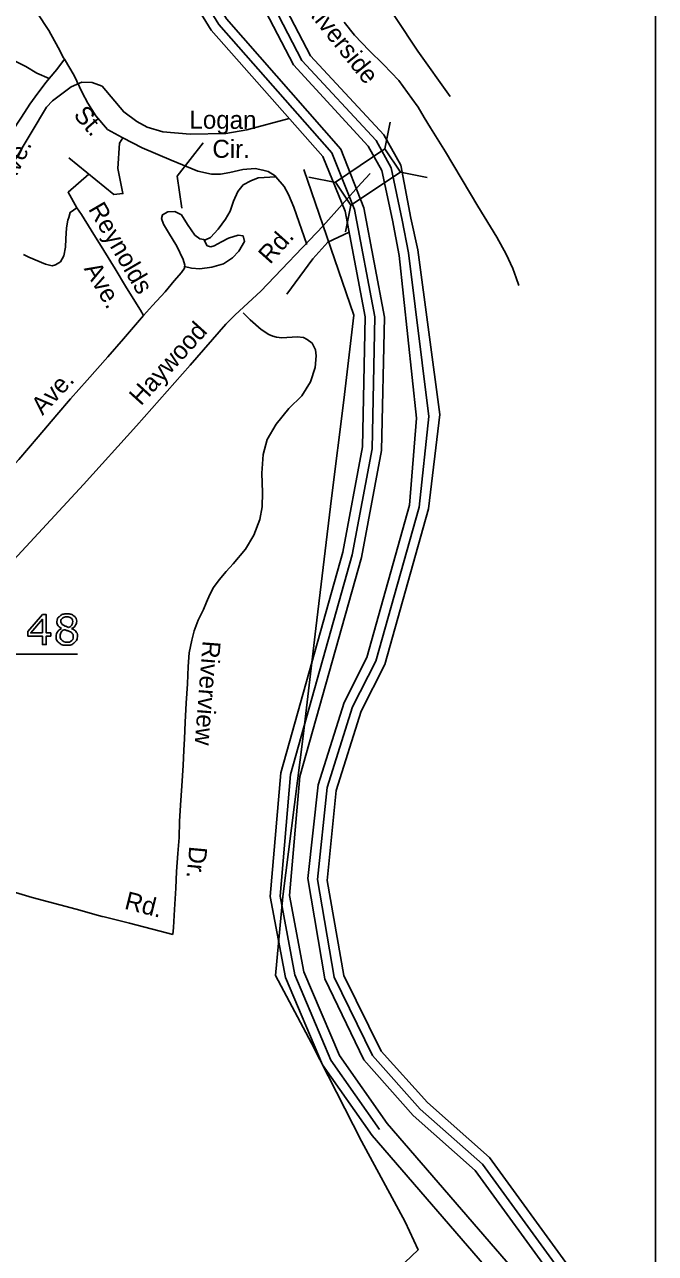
# Model space of a CAD drawing. Extents: x 925297 to 940193, y 663541 to 689899.
# Drawn here: x 929667 to 930192, y 687708 to 688730 of the extents above; entities that cross this region are included whole.
import ezdxf

# ---------------------------------------------------------------- set-up
doc = ezdxf.new("R2010")
doc.units = 0
doc.layers.add('Default', color=7, linetype='Continuous')
doc.layers.add('Sheet Title CELL', color=7, linetype='Continuous')

msp = doc.modelspace()

# ---------------------------------------------------------------- linework, layer by layer
at = {"layer": 'Default'}
for p, q in [((929971.4, 688649), (929967, 688626.8)), ((930002.1, 688603.1), (929979.9, 688607.5)), ((929926, 688598.8), (929903.8, 688603.2)), ((929938.6, 688580), (929934.2, 688557.8)), ((929623.4, 688206.6), (929711.2, 688206.6))]:
    msp.add_line(p, q, dxfattribs=at)
for points in [[(929515.7, 689501.3), (929516.7, 689464.3), (929576.5, 689382.4), (929587.9, 689370.1), (929666.2, 689275.9), (929674.1, 689250.4), (929678.7, 689194.9), (929688.2, 689040.4), (929697.8, 688993.3), (929716.5, 688955.8), (929737.2, 688888.6), (929775.8, 688816.5), (929828.8, 688730.2), (929922.8, 688623.5), (929941.6, 688576.4), (929958.6, 688487.1), (929956.3, 688377.5), (929939.7, 688289.2), (929888.3, 688106.6), (929879.7, 688005.5), (929891.9, 687940.2), (929922, 687869), (929962.6, 687811.5)], [(930095.1, 687665.9), (930073.2, 687695.8), (929968.9, 687816.4), (929929.1, 687872.9), (929899.6, 687942.6), (929887.7, 688005.9), (929896.1, 688105.1), (929947.4, 688287), (929964.2, 688376.1), (929966.6, 688486.9), (929949.5, 688577.9), (929930.2, 688626.5), (929835.3, 688735), (929782.7, 688820.5), (929744.6, 688891.7), (929724.1, 688958.2), (929705.4, 688995.9), (929696.1, 689041.5), (929686.7, 689195.4), (929691.8, 689223.6)], [(929691.8, 689223.6), (929702.1, 689209), (929724.4, 689187.5), (929716.8, 689144.9), (929713.4, 689061.3), (929725.4, 689008.2), (929810.8, 688838.3), (929844.4, 688786.2), (929890.8, 688696.7), (929953.1, 688629.1), (929964.3, 688608.9), (929973.2, 688567.4), (929978.8, 688538.1), (929993.3, 688402.8), (929987.5, 688330.5), (929952, 688204), (929933, 688166.4), (929911.3, 688098.1), (929902.9, 688020.3), (929916.9, 687936.8), (929949.5, 687869.5), (929990.4, 687823.1), (930042.1, 687777.3), (930109.6, 687684.7)], [(930085, 687652.8), (930060.4, 687686.3), (929956.3, 687806.5), (929915, 687865.1), (929884.2, 687937.9), (929871.6, 688005.1), (929880.3, 688108), (929932, 688291.4), (929948.4, 688379), (929950.6, 688487.3), (929933.8, 688574.9), (929915.4, 688620.5), (929822.4, 688725.4), (929768.8, 688812.5), (929729.7, 688885.5), (929708.8, 688953.5), (929690.1, 688990.6), (929680.2, 689039.4), (929670.8, 689194.5)], [(930119.8, 687697.9), (930054, 687788.2), (930002.3, 687833.8), (929963.8, 687876.6), (929932.7, 687939.6), (929918.8, 688018.6), (929926.5, 688093.3), (929947.2, 688159.2), (929967, 688198.1), (930003.3, 688327.4), (930012.8, 688406), (929994.3, 688542.8), (929988.5, 688569.2), (929980.2, 688613.3), (929966.1, 688638.6), (929905, 688704.1), (929858.3, 688794.3), (929825.1, 688845.5), (929741, 689011.9), (929729.4, 689060.7), (929732.2, 689140.7), (929745.7, 689190.3), (929739.1, 689193.8)], [(929892.7, 688906.4), (929904.8, 688878.4), (929921.8, 688835.2), (929938.3, 688799.1), (929948.6, 688781.4), (929957.3, 688764.4), (929994.4, 688708.1), (930021.2, 688670.3)], [(929700.3, 688701.3), (929699.6, 688702.5), (929695.2, 688711), (929687.3, 688725.2), (929677.5, 688739.9), (929667.3, 688754.8), (929657.1, 688770.5), (929647.3, 688785.6), (929642, 688797.5), (929640, 688805.9), (929640, 688813.7), (929641, 688821.2), (929646.5, 688838.4), (929651.7, 688850.4), (929657.1, 688858.7), (929661.8, 688862.3), (929664.4, 688863.5)], [(929851.3, 688790.3), (929897.9, 688700.4), (929959.6, 688633.8), (929972.3, 688611.1), (929981.3, 688567.4), (929986.6, 688540.5), (930003.4, 688404.4), (929995.4, 688329), (929959.5, 688201), (929940.1, 688162.8), (929918.9, 688095.7), (929910.9, 688019.4), (929924.8, 687938.2), (929956.6, 687873.1), (929996.3, 687828.5), (930048.1, 687782.7), (930114.7, 687691.3)], [(930078.3, 688513.3), (930076.2, 688519.5), (930073.4, 688527.4), (930067.9, 688539.3), (930060.1, 688553.4), (930044.4, 688579.3), (930017.3, 688624.4), (930004.8, 688644.3), (929999.6, 688652.9), (929994.6, 688661.4), (929989.5, 688668.6), (929978.6, 688683.7), (929965.9, 688696.9), (929953.8, 688708.5), (929941.7, 688721.3), (929933.2, 688732.3)], [(929687.7, 688685.3), (929677.4, 688689.9), (929668.1, 688695.2), (929653.8, 688702.4), (929644.4, 688705.8)], [(929700.3, 688701.3), (929694.1, 688692.8), (929687.7, 688685.3)], [(929749, 688635.9), (929748.4, 688636.2), (929736.1, 688643), (929726.5, 688654.2), (929719.9, 688664.8), (929715, 688673.6), (929708.3, 688687.7), (929700.3, 688701.3)], [(929687.7, 688685.3), (929685.2, 688682.2), (929678.1, 688673.1), (929671.5, 688664), (929664.5, 688653.2), (929656, 688640.2), (929649.2, 688627.8), (929638.6, 688609.3), (929627.7, 688591.3), (929618.1, 688574.3), (929613.9, 688566.2), (929613.8, 688566.1)], [(929659, 688617.5), (929685.4, 688661.4), (929690.4, 688666.8), (929706, 688678.3), (929714.9, 688682.4), (929723.3, 688682.1), (929731.6, 688679), (929749.7, 688657.5), (929760.6, 688649.5), (929769.2, 688644.8), (929782.3, 688641.1), (929805, 688639.1), (929834.7, 688639.6), (929852, 688642.6), (929887.4, 688652.1)], [(929749, 688635.9), (929746.1, 688631.5), (929744.7, 688610.4), (929749, 688589.7), (929741.5, 688588.9), (929703.9, 688619.4)], [(929876.3, 688603.5), (929875.6, 688604.3), (929869.8, 688608), (929865.4, 688609.2), (929858.9, 688610.4), (929848.8, 688609.8), (929837.9, 688607.2), (929830.3, 688605.9), (929822.7, 688605.8), (929811.4, 688608.2), (929789, 688617.4), (929765, 688627.8), (929749, 688635.9)], [(929815.7, 688631.7), (929794, 688604.2), (929797.9, 688577.6)], [(929954.8, 688606.4), (929947.2, 688598.4), (929915.6, 688562.8), (929863.6, 688508.5), (929842.4, 688488.8), (929834.7, 688481), (929805, 688446.9), (929760.3, 688396.5), (929716.1, 688347.7), (929651.4, 688277.6), (929637, 688263.2), (929592.3, 688213.2), (929577.7, 688195.5), (929570.1, 688171.9), (929567.9, 688147.4), (929562.4, 688100.2), (929560.8, 688077.2), (929557.1, 688049), (929557, 688048.9)], [(929710.6, 688577.9), (929703.3, 688590.7), (929720.6, 688605.8)], [(929899.5, 688609.8), (929941.2, 688488.5), (929932.7, 688418), (929922.6, 688336.3), (929909.4, 688227.9), (929898.9, 688138.6), (929882.1, 688005.3), (929876, 687939.5), (929906, 687883.3), (929947.4, 687801.8), (929983.8, 687734.7), (929994.6, 687711.4), (929955.2, 687674.1)], [(929876.3, 688603.5), (929861.6, 688602.6), (929855.3, 688600.3), (929848.9, 688596.8), (929844.6, 688591.3), (929841, 688583.2), (929838.1, 688575.1), (929834.3, 688568.4), (929828.2, 688560), (929821.9, 688553.2), (929817.8, 688551.3), (929816.4, 688551.5)], [(929902.1, 688547.2), (929891.2, 688578.3), (929886.7, 688589), (929883.2, 688595.4), (929876.3, 688603.5)], [(929710.6, 688577.9), (929705.2, 688574), (929704, 688569.7), (929703.2, 688567.4), (929702.1, 688561.2), (929701.5, 688551.9), (929701.2, 688545), (929699.8, 688538), (929697, 688533), (929693, 688530.4), (929690.1, 688529.7), (929684.7, 688531), (929670.6, 688536.9), (929666.4, 688538.9)], [(929766.2, 688488.4), (929763.5, 688492.7), (929758.8, 688500.2), (929751, 688512.8), (929742.5, 688527.1), (929733.1, 688542.3), (929722.7, 688559.3), (929714.5, 688572.2), (929710.6, 688577.9)], [(929816.4, 688551.5), (929812.9, 688551.9), (929808.8, 688555.2), (929802.8, 688563.9), (929797.6, 688571.9), (929792.2, 688574.7), (929786.3, 688574.6), (929781.9, 688572.1), (929781.2, 688569), (929782.8, 688564.2), (929787, 688557.2), (929793.8, 688546), (929799.1, 688534.7), (929800.5, 688530.1), (929800.3, 688528.9)], [(929816.4, 688551.5), (929819.1, 688546.3), (929822.2, 688545.3), (929825, 688546.2), (929831, 688549.4), (929836.9, 688552.6), (929844.8, 688555.1), (929849, 688554.5), (929850.1, 688549.9), (929845.5, 688541.9), (929840.2, 688536.1), (929832.7, 688531.1), (929822.9, 688528.5), (929813, 688527.1), (929806.1, 688527.7), (929800.3, 688528.9)], [(929885.5, 688506.1), (929907, 688535.4), (929919.5, 688549.3), (929937.1, 688557.5)], [(929800.3, 688528.9), (929800.1, 688527.6), (929797.8, 688524.1), (929791.6, 688517.2), (929784.2, 688507.9), (929773.6, 688496.6), (929766.2, 688488.4), (929766.2, 688488.4)], [(929766.2, 688488.4), (929749.4, 688469), (929736.3, 688454), (929719.2, 688434.6), (929705.5, 688418.9), (929694, 688405.8), (929678.6, 688387.5), (929662.3, 688368.6), (929647.2, 688351.6), (929632.6, 688334.7), (929585.2, 688279.9), (929560.1, 688251.6), (929556, 688248.1)], [(929849.1, 688490.5), (929854.8, 688484.8), (929864.1, 688476.6), (929870.4, 688472.5), (929873.8, 688471), (929876.9, 688470.2), (929881.2, 688469.6), (929894, 688470.5), (929899.3, 688469.9), (929902.4, 688468.2), (929906.5, 688465.2), (929909.2, 688459.7), (929909.8, 688454.7), (929908.9, 688445), (929905, 688433.1), (929897.9, 688421.5), (929887.1, 688411), (929876.5, 688397.8), (929869.1, 688385.1), (929865.7, 688372.7), (929864.5, 688357.3), (929865.2, 688341.2), (929864.8, 688329.2), (929863, 688318.7), (929858, 688305.7), (929851, 688294.1), (929840.7, 688281.9), (929834.8, 688275.3), (929829, 688268.5), (929824.4, 688262.2), (929821.4, 688256.4), (929818.6, 688249.8), (929815.9, 688243.9), (929811.7, 688234.9), (929808.2, 688226), (929806.2, 688218.4), (929804.2, 688207.7), (929803.2, 688196.4), (929802.7, 688182.1), (929801.7, 688165.9), (929800.7, 688150.1), (929800.1, 688136.4), (929799.7, 688126.8), (929799, 688114), (929798.1, 688097.3), (929797, 688081.1), (929796.1, 688067.5), (929795.7, 688054.3), (929794.7, 688040.9), (929793.7, 688025.9), (929792.9, 688012), (929791.9, 687994.3), (929791, 687979.4), (929790.6, 687973.7)], [(929688.9, 688221.7), (929685.2, 688221.7), (929685.2, 688214.6), (929682, 688214.6), (929682, 688221.7), (929670, 688221.7), (929670, 688225.5), (929682.1, 688239.6), (929685.2, 688239.6), (929685.2, 688224.4), (929688.9, 688224.4), (929688.9, 688221.7)], [(929682, 688224.4), (929682, 688235.7), (929672.3, 688224.4), (929682, 688224.4)], [(929698, 688228), (929698, 688228.1)], [(929706.3, 688228), (929706.3, 688227.9)], [(929555.5, 688039.6), (929559.9, 688037.8), (929588, 688029.5), (929615.5, 688021.3), (929628.3, 688017.6), (929639.8, 688014.3), (929654.1, 688010.1), (929667.9, 688006)], [(929667.9, 688006), (929673.6, 688004.3), (929710, 687994.6), (929728.8, 687989.4)], [(929728.8, 687989.4), (929731.8, 687988.5), (929733.3, 687988.2)], [(929733.3, 687988.2), (929754.4, 687982.9), (929785.2, 687975.1), (929790.6, 687973.7)]]:
    msp.add_lwpolyline(points, dxfattribs=at)
msp.add_lwpolyline([(929979.9, 688607.5), (929938.7, 688579.9), (929925.8, 688599.2), (929967, 688626.8)], close=True, dxfattribs=at)
for points in [[(929698, 688228.1), (929696, 688229.2), (929695, 688230.4), (929694.1, 688231.7), (929694.1, 688233.6), (929694.1, 688236.5), (929696.4, 688238.3), (929698.7, 688240.2), (929702.3, 688240.2), (929706, 688240.2), (929708.3, 688238.4), (929710.5, 688236.6), (929710.5, 688233.9), (929710.5, 688232.2), (929709.4, 688230.5), (929708.4, 688228.9), (929706.3, 688228)], [(929707.2, 688233.8), (929707.2, 688235.6), (929705.8, 688236.7), (929704.4, 688237.7), (929702.3, 688237.7), (929700.1, 688237.7), (929698.8, 688236.7), (929697.4, 688235.7), (929697.4, 688234), (929697.4, 688232.8), (929698.1, 688231.9), (929698.8, 688231), (929700.2, 688230.4), (929700.8, 688230.1), (929702, 688229.6), (929703.1, 688229.1), (929704.2, 688228.8), (929705.9, 688229.9), (929706.5, 688231.1), (929707.2, 688232.3), (929707.2, 688233.8)], [(929711.2, 688221.6), (929711.2, 688218.4), (929708.6, 688216.2), (929706.1, 688214.1), (929702.3, 688214.1), (929698.2, 688214.1), (929695.8, 688216.2), (929693.4, 688218.3), (929693.4, 688221.5), (929693.4, 688223.6), (929694.6, 688225.3), (929695.8, 688227), (929698, 688228)], [(929707.7, 688221.3), (929707.7, 688222.8), (929707, 688223.8), (929706.3, 688224.7), (929704.4, 688225.6), (929703.6, 688226), (929702.6, 688226.3), (929701.7, 688226.6), (929700.1, 688227.2), (929698.6, 688226.4), (929697.7, 688225), (929696.8, 688223.6), (929696.8, 688221.8), (929696.8, 688219.5), (929698.4, 688218.1), (929699.9, 688216.6), (929702.3, 688216.6), (929704.8, 688216.6), (929706.2, 688217.8), (929707.7, 688219.1), (929707.7, 688221.3)], [(929706.3, 688227.9), (929708.7, 688226.9), (929709.9, 688225.4), (929711.2, 688223.9), (929711.2, 688221.6)]]:
    msp.add_open_spline(points, degree=3, dxfattribs=at)
at = {"layer": 'Sheet Title CELL'}
msp.add_lwpolyline([(927148.4, 689501.3), (930192.1, 689501.3), (930192.1, 687400.3), (927148.4, 687400.3)], close=True, dxfattribs=at)

# ---------------------------------------------------------------- texts
at = {"layer": 'Default'}
for s, rotation, p in [('Riverside', 308.7695, (929898.8, 688744.6)), ('St.', 311.0908, (929707.2, 688654.6)), ('Logan', 359.6467, (929804.3, 688643.7)), ('Ave.', 64.3653, (929656.2, 688594.7)), ('Cir.', 359.7103, (929823.4, 688619.4)), ('Reynolds', 300.1998, (929719.8, 688576.9)), ('Rd.', 48.1708, (929871.4, 688530.2)), ('Ave.', 300.1998, (929716.2, 688527.2)), ('Haywood', 47.8419, (929763.9, 688412.6)), ('Ave.', 46.8756, (929682.1, 688404.7)), ('Riverview', 265.5639, (929815.4, 688218.2)), ('Dr.', 264.7582, (929804.3, 688047.4)), ('Rd.', 345.7939, (929749.5, 687995.1))]:
    msp.add_text(s, height=15, rotation=rotation, dxfattribs=at).set_placement(p)

doc.saveas('drawing.dxf')
